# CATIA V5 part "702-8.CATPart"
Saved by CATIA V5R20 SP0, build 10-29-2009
Part number: 702-8
Source: Unknown
Property "ARTICLENO": "702-8"
Property "BOMINFO": "702-8"
Property "CODE": "702-8"
Property "L": "300.000"
Property "LINA": "702-8"
Property "NB": "702-8"
Property "NBSYN": "$CODE."
Property "NN": "702"
Property "SUPPLIER": "CF"
Bounding box of the stored display mesh (mm): x -107 to 0, y 0 to 300, z -15 to 15
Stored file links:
  C:\Users\Utente\Desktop\3D files 702\702-8.CATPart
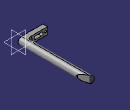
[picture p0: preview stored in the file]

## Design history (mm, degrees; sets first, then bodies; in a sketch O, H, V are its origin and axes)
Body1 "Geometry.1" (main body)
  Solid1 "702-8.catpart": solid without history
